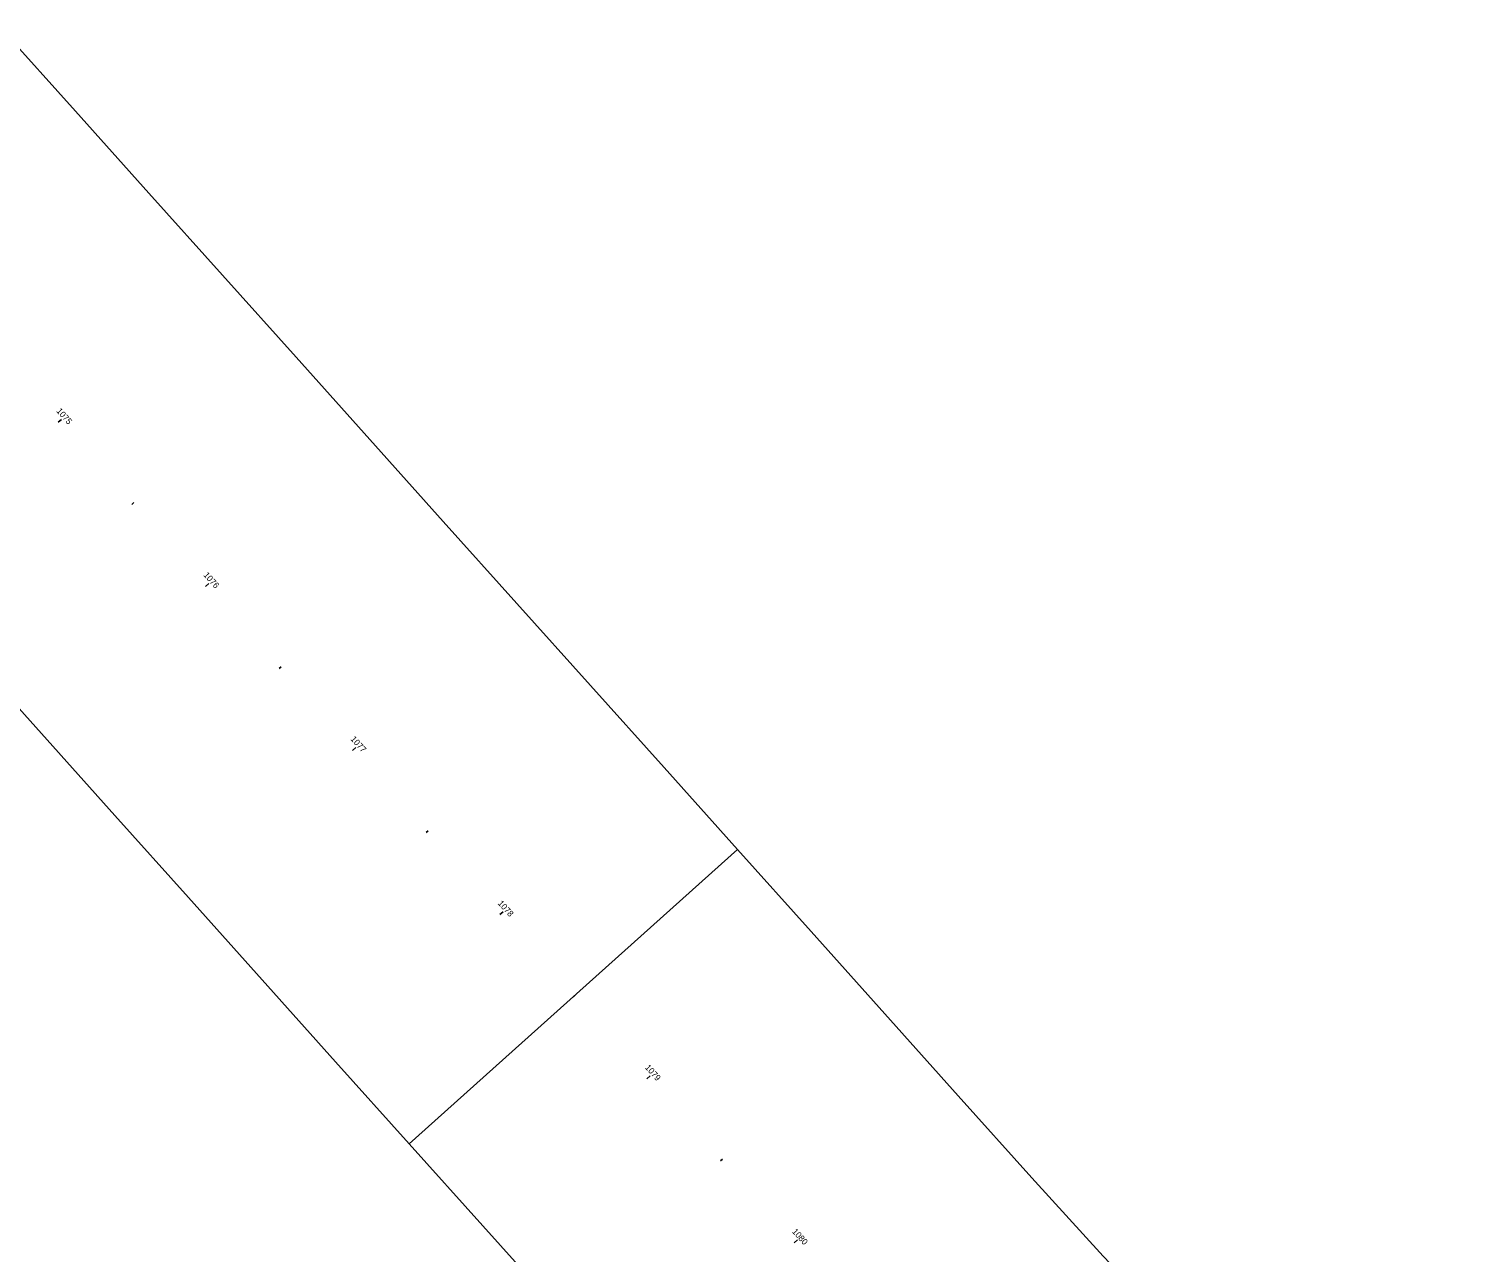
# Model space of a CAD drawing. Extents: x 1846275 to 1850613, y 577927 to 582526.
# Drawn here: x 1849149 to 1849808, y 579068 to 579624 of the extents above; entities that cross this region are included whole.
import ezdxf

# ---------------------------------------------------------------- set-up
doc = ezdxf.new("R2010")
doc.units = 0
doc.layers.add('GE_P_Alignment_100_Cardinal_Points', color=7, linetype='Continuous')
doc.layers.add('SH_Named_Boundary', color=7, linetype='Continuous')

msp = doc.modelspace()

# ---------------------------------------------------------------- linework, layer by layer
at = {"layer": 'GE_P_Alignment_100_Cardinal_Points'}
for p, q in [((1849161.93, 579445.3), (1849163.42, 579446.64)), ((1849195.31, 579408.07), (1849196.2, 579408.87)), ((1849228.68, 579370.84), (1849230.17, 579372.17)), ((1849262.05, 579333.61), (1849262.95, 579334.41)), ((1849295.43, 579296.37), (1849296.92, 579297.71)), ((1849328.8, 579259.14), (1849329.69, 579259.94)), ((1849362.17, 579221.91), (1849363.66, 579223.24)), ((1849395.55, 579184.68), (1849396.44, 579185.48)), ((1849428.92, 579147.45), (1849430.41, 579148.78)), ((1849462.29, 579110.21), (1849463.19, 579111.01)), ((1849495.67, 579072.98), (1849497.16, 579074.32))]:
    msp.add_line(p, q, dxfattribs=at)
at = {"layer": 'SH_Named_Boundary'}
for points in [[(1849136.29, 579623.73), (1848987.36, 579490.24), (1849020.73, 579453.01), (1849054.11, 579415.78), (1849087.48, 579378.55), (1849120.85, 579341.31), (1849154.23, 579304.08), (1849187.6, 579266.85), (1849220.97, 579229.62), (1849254.35, 579192.38), (1849287.72, 579155.15), (1849321.09, 579117.92), (1849470.02, 579251.41), (1849436.65, 579288.65), (1849403.27, 579325.88), (1849369.9, 579363.11), (1849336.53, 579400.34), (1849303.15, 579437.57), (1849269.78, 579474.81), (1849236.41, 579512.04), (1849203.03, 579549.27), (1849169.66, 579586.5)], [(1849470.02, 579251.41), (1849321.09, 579117.92), (1849354.47, 579080.69), (1849387.84, 579043.46), (1849421.21, 579006.22), (1849454.59, 578968.99), (1849489.61, 578930.63), (1849525.52, 578892.89), (1849562.22, 578855.92), (1849599.69, 578819.73), (1849637.9, 578784.32), (1849676.85, 578749.73), (1849808.1, 578900.63), (1849772.28, 578932.45), (1849737.14, 578965.01), (1849702.69, 578998.29), (1849668.94, 579032.29), (1849635.91, 579066.99), (1849603.52, 579102.48), (1849570.14, 579139.72), (1849536.77, 579176.95), (1849503.4, 579214.18)]]:
    msp.add_lwpolyline(points, close=True, dxfattribs=at)

# ---------------------------------------------------------------- texts
at = {"layer": 'GE_P_Alignment_100_Cardinal_Points'}
for s, p in [('1075', (1849160.84, 579450.26)), ('1076', (1849227.56, 579375.84)), ('1077', (1849294.26, 579301.42)), ('1078', (1849361.06, 579226.89)), ('1079', (1849427.82, 579152.42)), ('1080', (1849494.55, 579077.97))]:
    msp.add_text(s, height=2.8, rotation=311.8718, dxfattribs=at).set_placement(p)

doc.saveas('drawing.dxf')
